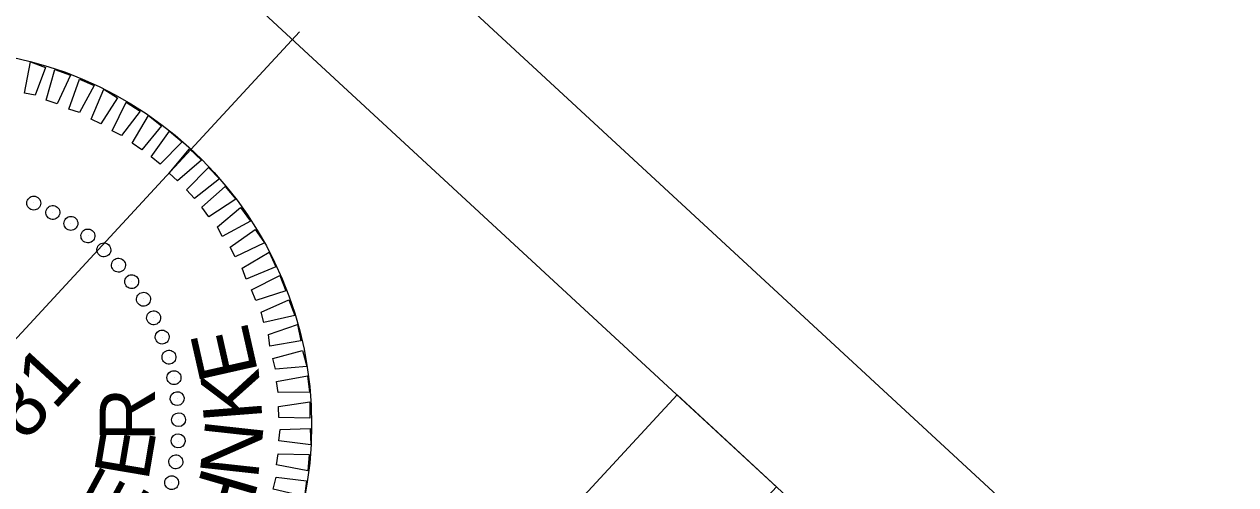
# Model space of a CAD drawing. Extents: x 1768274 to 1769121, y 999922 to 1000687.
# Drawn here: x 1768981.8 to 1769004.61, y 1000283.92 to 1000292.6 of the extents above; entities that cross this region are included whole.
import ezdxf

# ---------------------------------------------------------------- set-up
doc = ezdxf.new("R2010")
doc.units = 0
for name, color, linetype in [('E_NCDOT_Terrain_Model_Contour_Imported', 7, 'Continuous'), ('E_NCDOT_Terrain_Model_Contour_Major', 7, 'Continuous'), ('E_NCDOT_Terrain_Model_Spot_Elevation', 7, 'Continuous'), ('E_NCDOT_Terrain_Model_Triangle_Vertices', 7, 'Continuous'), ('E_NCDOT_Terrain_Model_Void', 7, 'Continuous')]:
    doc.layers.add(name, color=color, linetype=linetype)

msp = doc.modelspace()

# ---------------------------------------------------------------- linework, layer by layer
at = {"layer": 'E_NCDOT_Terrain_Model_Contour_Imported'}
msp.add_line((1768986.989, 1000292.453), (1768973.311, 1000277.656), dxfattribs=at)
msp.add_circle((1768980.15, 1000285.055), 7.065, dxfattribs=at)
at = {"layer": 'E_NCDOT_Terrain_Model_Contour_Major'}
msp.add_line((1769116.231, 1000172.715), (1768961.29, 1000315.942), dxfattribs=at)
msp.add_lwpolyline([(1768980.521, 1000270.929), (1768994.098, 1000285.617), (1768995.969, 1000283.888), (1768982.392, 1000269.2)], close=True, dxfattribs=at)
at = {"layer": 'E_NCDOT_Terrain_Model_Spot_Elevation'}
msp.add_lwpolyline([(1768729.032, 1000071.305), (1768959.819, 1000320.98), (1769121.372, 1000171.648), (1768890.585, 999921.973)], close=True, dxfattribs=at)
at = {"layer": 'E_NCDOT_Terrain_Model_Triangle_Vertices'}
msp.add_line((1769121.372, 1000171.648), (1768959.819, 1000320.98), dxfattribs=at)
at = {"layer": 'E_NCDOT_Terrain_Model_Void'}
for p, q in [((1768981.984, 1000289.238), (1768981.984, 1000289.238)), ((1768982.339, 1000289.058), (1768982.339, 1000289.058)), ((1768982.683, 1000288.84), (1768982.683, 1000288.84)), ((1768983.007, 1000288.614), (1768983.007, 1000288.614)), ((1768983.307, 1000288.349), (1768983.307, 1000288.349)), ((1768983.583, 1000288.057), (1768983.583, 1000288.057)), ((1768983.827, 1000287.745), (1768983.827, 1000287.745)), ((1768984.052, 1000287.425), (1768984.052, 1000287.425)), ((1768984.246, 1000287.072), (1768984.246, 1000287.072)), ((1768984.402, 1000286.705), (1768984.402, 1000286.705)), ((1768984.539, 1000286.33), (1768984.539, 1000286.33)), ((1768984.626, 1000285.941), (1768984.626, 1000285.941)), ((1768984.693, 1000285.544), (1768984.693, 1000285.544)), ((1768984.715, 1000285.152), (1768984.715, 1000285.152)), ((1768984.711, 1000284.746), (1768984.711, 1000284.746)), ((1768984.662, 1000284.358), (1768984.662, 1000284.358)), ((1768984.581, 1000283.962), (1768984.581, 1000283.962))]:
    msp.add_line(p, q, dxfattribs=at)
for points in [[(1768981.807, 1000291.298), (1768981.919, 1000291.888), (1768982.206, 1000291.784), (1768982.008, 1000291.261)], [(1768982.218, 1000291.166), (1768982.382, 1000291.746), (1768982.676, 1000291.635), (1768982.426, 1000291.097)], [(1768982.643, 1000290.996), (1768982.846, 1000291.564), (1768983.121, 1000291.446), (1768982.845, 1000290.933)], [(1768983.063, 1000290.806), (1768983.304, 1000291.376), (1768983.562, 1000291.212), (1768983.246, 1000290.723)], [(1768983.457, 1000290.59), (1768983.72, 1000291.128), (1768983.984, 1000290.958), (1768983.635, 1000290.5)], [(1768983.834, 1000290.354), (1768984.142, 1000290.875), (1768984.388, 1000290.685), (1768984.019, 1000290.232)], [(1768984.192, 1000290.097), (1768984.54, 1000290.581), (1768984.779, 1000290.384), (1768984.364, 1000289.962)], [(1768984.532, 1000289.795), (1768984.914, 1000290.248), (1768985.141, 1000290.038), (1768984.692, 1000289.647)], [(1768984.86, 1000289.479), (1768985.275, 1000289.901), (1768985.483, 1000289.684), (1768985.008, 1000289.318)], [(1768985.15, 1000289.149), (1768985.585, 1000289.54), (1768985.788, 1000289.303), (1768985.279, 1000288.968)], [(1768985.441, 1000288.781), (1768985.878, 1000289.146), (1768986.062, 1000288.889), (1768985.532, 1000288.598)], [(1768985.682, 1000288.398), (1768986.152, 1000288.732), (1768986.329, 1000288.481), (1768985.773, 1000288.214)], [(1768985.91, 1000288.001), (1768986.413, 1000288.304), (1768986.54, 1000288.026), (1768985.982, 1000287.798)], [(1768986.08, 1000287.595), (1768986.617, 1000287.868), (1768986.732, 1000287.576), (1768986.166, 1000287.393)], [(1768986.264, 1000287.177), (1768986.784, 1000287.404), (1768986.898, 1000287.112), (1768986.317, 1000286.98)], [(1768986.403, 1000286.751), (1768986.95, 1000286.94), (1768987.013, 1000286.634), (1768986.425, 1000286.533)], [(1768986.485, 1000286.304), (1768987.046, 1000286.455), (1768987.123, 1000286.149), (1768986.532, 1000286.1)], [(1768986.554, 1000285.869), (1768987.136, 1000285.975), (1768987.174, 1000285.668), (1768986.588, 1000285.664)], [(1768986.592, 1000285.4), (1768987.181, 1000285.487), (1768987.18, 1000285.178), (1768986.6, 1000285.194)], [(1768986.622, 1000284.963), (1768987.188, 1000284.985), (1768987.2, 1000284.677), (1768986.598, 1000284.75)], [(1768986.582, 1000284.504), (1768987.168, 1000284.495), (1768987.142, 1000284.185), (1768986.551, 1000284.297)], [(1768986.548, 1000284.065), (1768987.117, 1000283.997), (1768987.083, 1000283.706), (1768986.492, 1000283.844)]]:
    msp.add_lwpolyline(points, close=True, dxfattribs=at)
for centre, major_axis in [((1768981.984, 1000289.228), (0.053, 0.12)), ((1768982.342, 1000289.052), (0.063, 0.115)), ((1768982.682, 1000288.846), (0.073, 0.109)), ((1768983.003, 1000288.61), (0.082, 0.102)), ((1768983.303, 1000288.348), (0.0906, 0.0947)), ((1768983.578, 1000288.06), (0.0985, 0.0864)), ((1768983.827, 1000287.749), (0.106, 0.077)), ((1768984.049, 1000287.418), (0.112, 0.068)), ((1768984.24, 1000287.069), (0.118, 0.058)), ((1768984.401, 1000286.705), (0.122, 0.048)), ((1768984.529, 1000286.327), (0.126, 0.037)), ((1768984.623, 1000285.941), (0.129, 0.026)), ((1768984.684, 1000285.547), (0.13, 0.014)), ((1768984.71, 1000285.15), (0.131, 0.003)), ((1768984.701, 1000284.751), (0.131, -0.009)), ((1768984.658, 1000284.356), (0.13, -0.02)), ((1768984.58, 1000283.965), (0.127, -0.031))]:
    msp.add_ellipse(centre, major_axis=major_axis, ratio=0.999708, dxfattribs=at)

# ---------------------------------------------------------------- texts
for s, height, rotation, p in [('E', 1.102, 102.7443, (1768986.212, 1000286.037)), ('046981', 1.0918, 47.2512, (1768979.614, 1000282.327)), ('K', 1.104, 94.4603, (1768986.291, 1000285.153)), ('R', 1.038, 89.7326, (1768984.261, 1000284.742)), ('N', 1.103, 83.7345, (1768986.202, 1000284.007)), ('E', 1.036, 80.3753, (1768984.136, 1000283.977)), ('E', 1.029, 61.663, (1768983.742, 1000283.027)), ('H', 1.1, 73.7505, (1768985.93, 1000282.973))]:
    msp.add_text(s, height=height, rotation=rotation, dxfattribs=at).set_placement(p)

doc.saveas('drawing.dxf')
